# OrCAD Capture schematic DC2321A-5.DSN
size Custom; title: DC2321A: DUST APPLICATION WITH E-INK DISPLAY; rev: 5; note: DEMO CIRCUIT 2321A
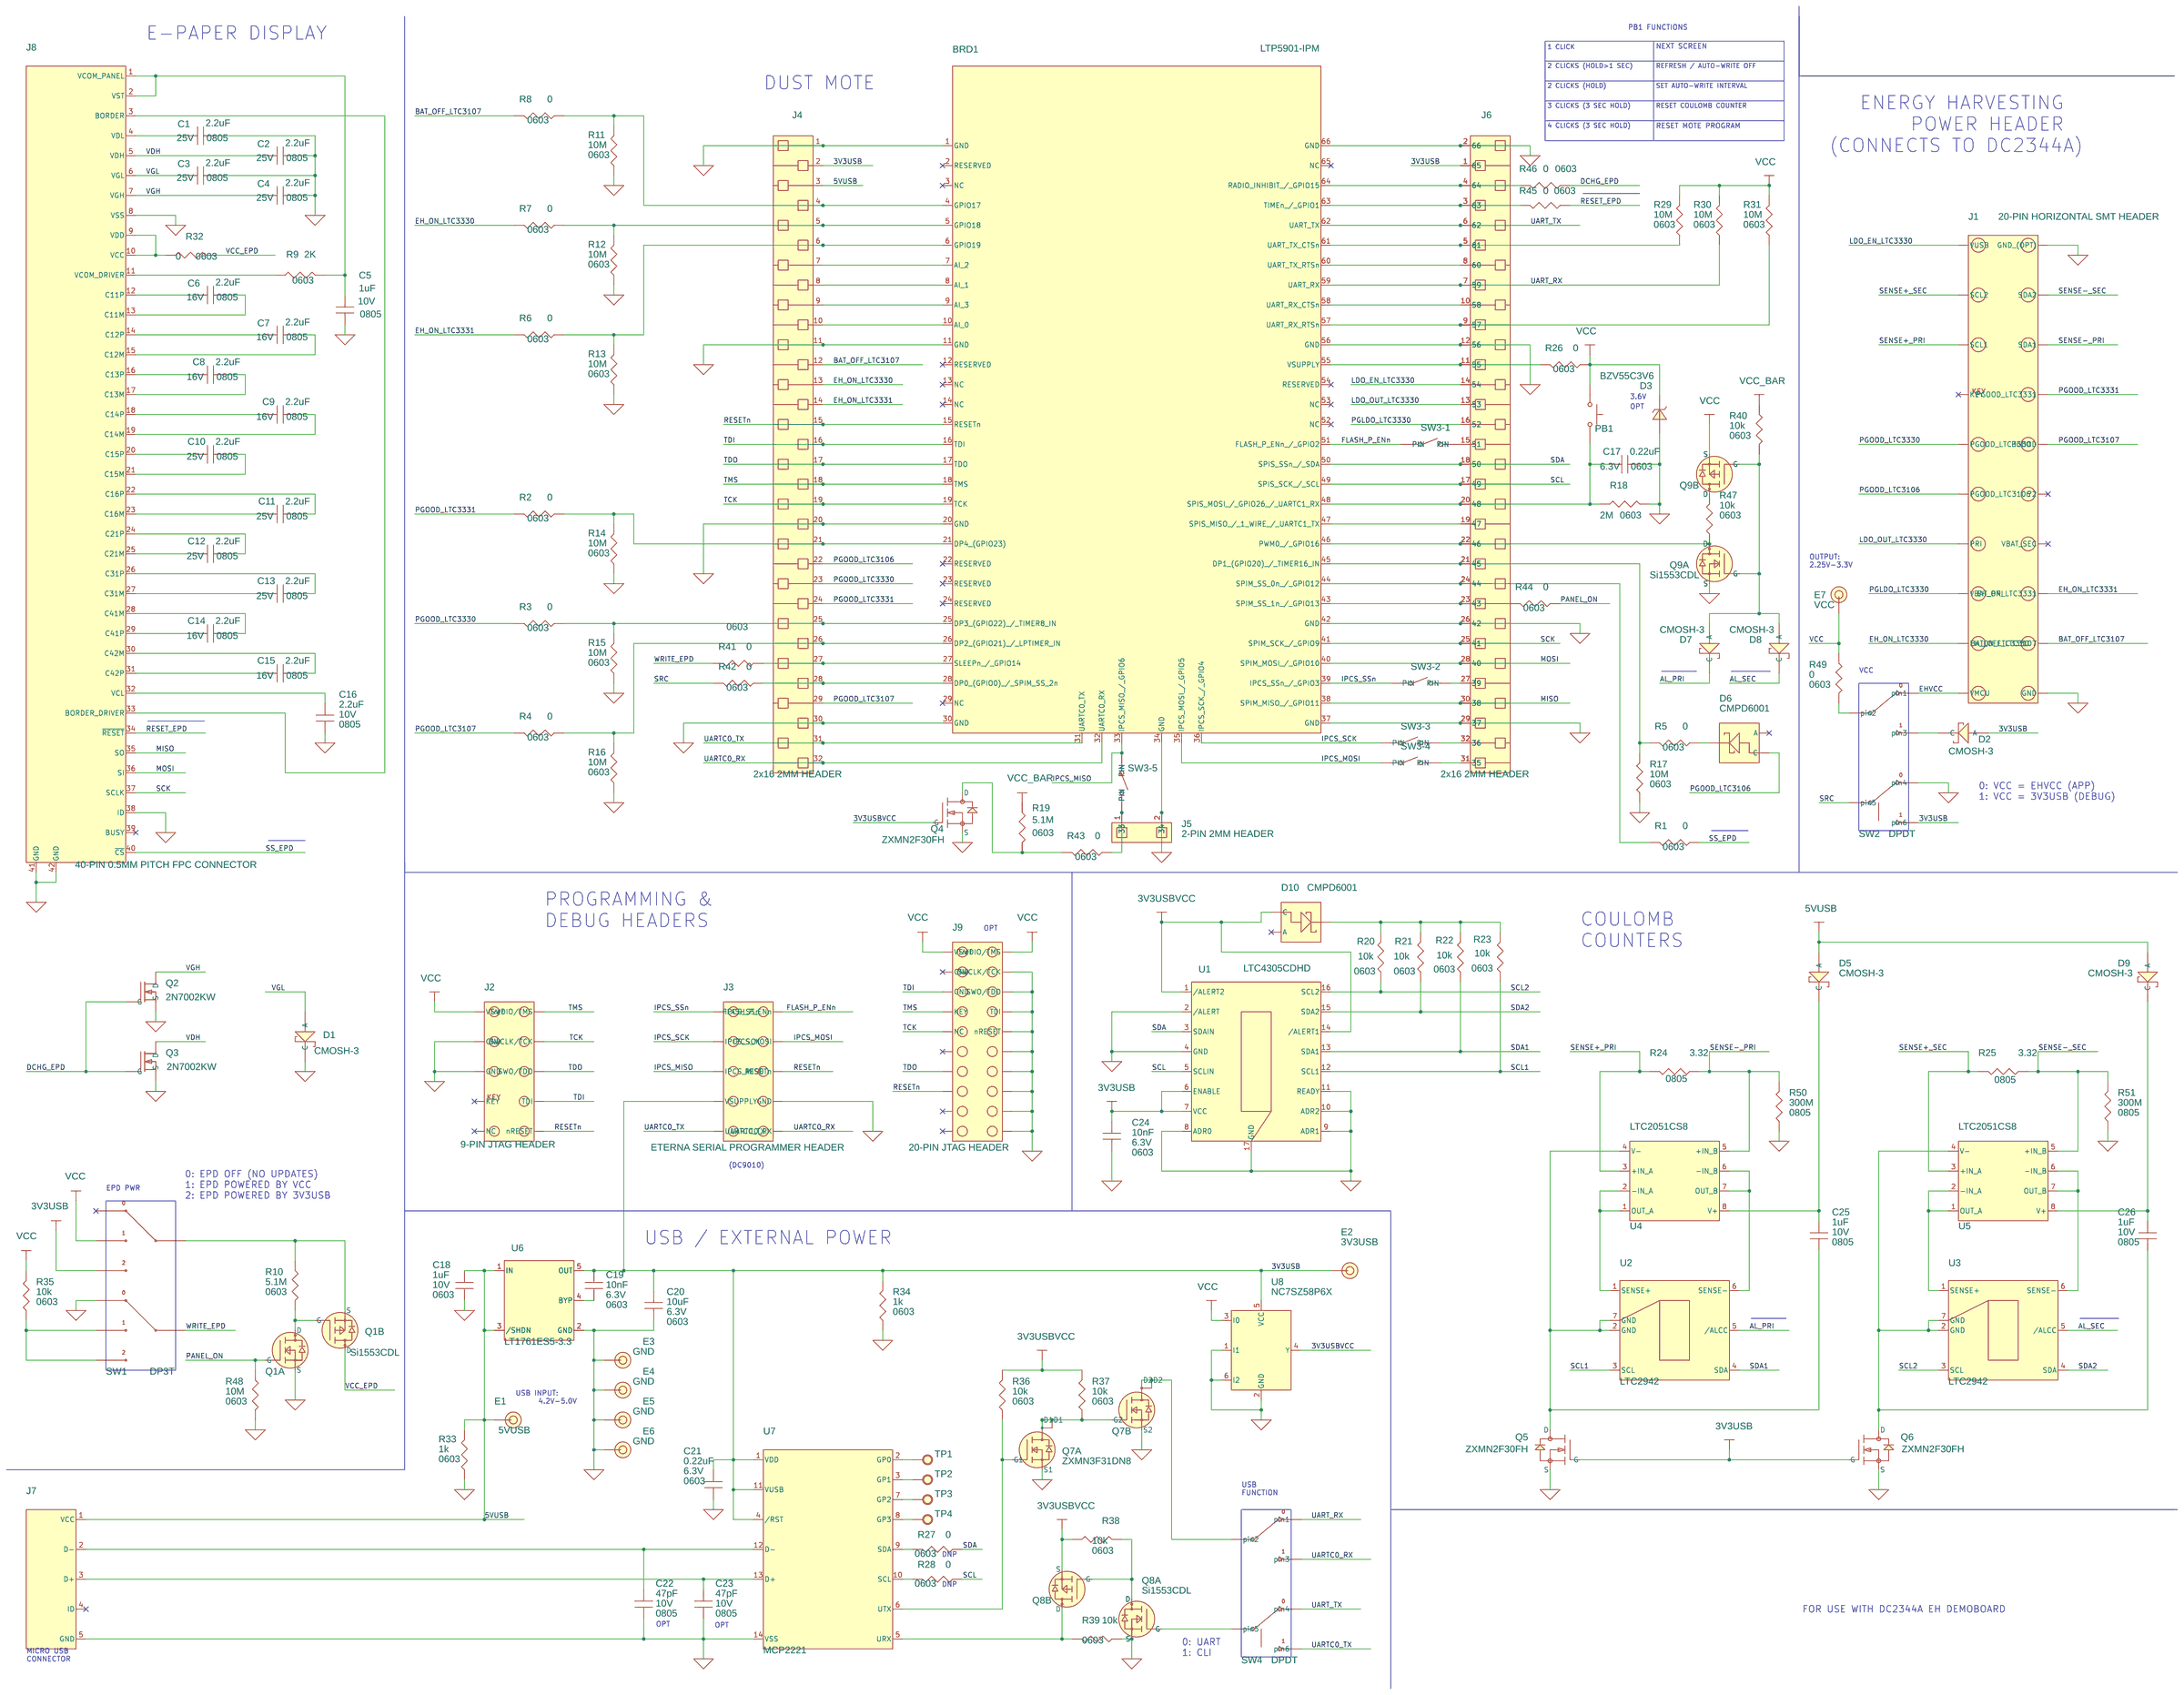
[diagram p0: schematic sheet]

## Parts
BRD1  LTP5901-IPM  [LTP5901-IPM/LTP5902-IPM]
C1  2.2uF  [0805]
C2  2.2uF  [0805]
C3  2.2uF  [0805]
C4  2.2uF  [0805]
C5  1uF  [0805]
C6  2.2uF  [0805]
C7  2.2uF  [0805]
C8  2.2uF  [0805]
C9  2.2uF  [0805]
C10  2.2uF  [0805]
C11  2.2uF  [0805]
C12  2.2uF  [0805]
C13  2.2uF  [0805]
C14  2.2uF  [0805]
C15  2.2uF  [0805]
C16  2.2uF  [0805]
C17  0.22uF  [0603]
C18  1uF  [0603]
C19  10nF  [0603]
C20  10uF  [0603]
C21  0.22uF  [0603]
C22  47pF  [0805]
C23  47pF  [0805]
C24  10nF  [0603]
C25  1uF  [0805]
C26  1uF  [0805]
D1  CMOSH-3  [SOD-523]
D2  CMOSH-3  [SOD-523]
D3  BZV55C3V6  [SOD80]
D5  CMOSH-3  [SOD-523]
D6  CMPD6001  [SOT-23]
D7  CMOSH-3  [SOD-523]
D8  CMOSH-3  [SOD-523]
D9  CMOSH-3  [SOD-523]
D10  CMPD6001  [SOT-23]
E1  5VUSB  [MILL-MAX-2308]
E2  3V3USB  [MILL-MAX-2308]
E3  GND  [MILL-MAX-2308]
E4  GND  [MILL-MAX-2308]
E5  GND  [MILL-MAX-2308]
E6  GND  [MILL-MAX-2308]
E7  VCC  [MILL-MAX-2308]
J1  20-PIN HORIZONTAL SMT HEADER  [HEADER2X10MS2.54]
J2  9-PIN JTAG HEADER  [HDR-WURTH-62201021121-2X5-1.27MM_W_KEY]
J3  ETERNA SERIAL PROGRAMMER HEADER  [HDR-WURTH-62001021121-2X5-2MM-ETERNA_HDR]
J4  2x16 2MM HEADER  [HDR-WURTH-62003221821-2X16-2MM]
J5  2-PIN 2MM HEADER  [WURTH-62000211821-2P-2MM]
J6  2x16 2MM HEADER  [HDR-WURTH-62003221821-2X16-2MM]
J7  MICRO USB CONNECTOR  [WURTH-629105136821-MICRO-USB-2.0]
J8  40-PIN 0.5MM PITCH FPC CONNECTOR  [WURTH-68714014522-40P_FPC_CONNECTOR]
J9  20-PIN JTAG HEADER  [HDR-SBH11-NBPC-D10-SM-BK]
PB1  1ApanelmountSPST  [SW-WURTH-434-111-025-826]
Q1  Si1553DL  [SC70-6]  (sections A,B)
Q2  2N7002KW  [SC70-3]
Q3  2N7002KW  [SC70-3]
Q4  ZXMN2F30FH  [ZETEX-SOT23]
Q5  ZXMN2F30FH  [ZETEX-SOT23]
Q6  ZXMN2F30FH  [ZETEX-SOT23]
Q7  ZXMN3F31DN8  [SO8]  (sections A,B)
Q8  Si1553DL  [SC70-6]  (sections A,B)
Q9  Si1553DL  [SC70-6]  (sections A,B)
R1  0  [0603]
R2  0  [0603]
R3  0  [0603]
R4  0  [0603]
R5  0  [0603]
R6  0  [0603]
R7  0  [0603]
R8  0  [0603]
R9  2K  [0603]
R10  5.1M  [0603]
R11  10M  [0603]
R12  10M  [0603]
R13  10M  [0603]
R14  10M  [0603]
R15  10M  [0603]
R16  10M  [0603]
R17  10M  [0603]
R18  2M  [0603]
R19  5.1M  [0603]
R20  10k  [0603]
R21  10k  [0603]
R22  10k  [0603]
R23  10k  [0603]
R24  3.32  [0805]
R25  3.32  [0805]
R26  0  [0603]
R27  0  [0603]
R28  0  [0603]
R29  10M  [0603]
R30  10M  [0603]
R31  10M  [0603]
R32  0  [0603]
R33  1k  [0603]
R34  1k  [0603]
R35  10k  [0603]
R36  10k  [0603]
R37  10k  [0603]
R38  10k  [0603]
R39  10k  [0603]
R40  10k  [0603]
R41  0  [0603]
R42  0  [0603]
R43  0  [0603]
R44  0  [0603]
R45  0  [0603]
R46  0  [0603]
R47  10k  [0603]
R48  10M  [0603]
R49  0  [0603]
R50  300M  [0805]
R51  300M  [0805]
SW1  DP3T  [SLIDE_SW-DP3T-CL-SB-23A-02T]
SW2  DPDT  [SLIDE-SW-CL-SB-22A]
SW3  1ApanelmountSPST  [WURTH-SW-416131160805]  (sections -1,-2,-3,-4,-5)
SW4  DPDT  [SLIDE-SW-CL-SB-22A]
TP1  Large Turret_1  [TP]
TP2  Large Turret_1  [TP]
TP3  Large Turret_1  [TP]
TP4  Large Turret_1  [TP]
U1  LTC4305CDHD  [DFN(16)(DHD)5MMX4MM]
U2  LTC2942  [DCB6DFN2X3]
U3  LTC2942  [DCB6DFN2X3]
U4  LTC2051CS8  [S8]
U5  LTC2051CS8  [S8]
U6  LT1761ES5-3.3  [SOT23-S5]
U7  MCP2221  [TSSOP14_MCP2221]
U8  NC7SZ58P6X  [SC-70]

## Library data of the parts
BRD1 = LTP5901-IPM_8
C1 = Capacitor_2_12: Voltage Rating: 25V
C2 = Capacitor_2_22: Voltage Rating: 25V
C3 = Capacitor_2_9: Voltage Rating: 25V
C4 = Capacitor_2_10: Voltage Rating: 25V
C5 = Capacitor_2_21: Voltage Rating: 10V
C6 = Capacitor_2_11: Voltage Rating: 16V
C7 = Capacitor_2_19: Voltage Rating: 16V
C8 = Capacitor_2_14: Voltage Rating: 16V
C9 = Capacitor_2_6: Voltage Rating: 16V
C10 = Capacitor_2_16: Voltage Rating: 25V
C11 = Capacitor_2_13: Voltage Rating: 25V
C12 = Capacitor_2_4: Voltage Rating: 25V
C13 = Capacitor_2_25: Voltage Rating: 25V
C14 = Capacitor_2_18: Voltage Rating: 16V
C15 = Capacitor_2_1: Voltage Rating: 16V
C16 = Capacitor_2_7: Voltage Rating: 10V
C17 = Capacitor_2_24: Voltage Rating: 6.3V
C18 = Capacitor_2: Voltage Rating: 10V
C19 = Capacitor_2_20: Voltage Rating: 6.3V
C20 = Capacitor_2_23: Voltage Rating: 6.3V
C21 = Capacitor_2_8: Voltage Rating: 6.3V
C22 = Capacitor_2_15: Voltage Rating: 10V
C23 = Capacitor_2_17: Voltage Rating: 10V
C24 = Capacitor_2_5: Voltage Rating: 6.3V
C25 = Capacitor_2_2: Voltage Rating: 10V
C26 = Capacitor_2_3: Voltage Rating: 10V
D1 D2 D5 D7-D9 = CMSH3-MA
D3 = AD589_TO_1
D6 D10 = CMSH3-MA_7
E1-E7 = E_1: STATUS: 1.6V, 1.8V, 2.0V OR 2.5V @ 15A
J1 = 20-Pin_Horizontal_SMTHeader_7
J2 = 9-PIN_JTAG_CONNECTOR_3
J3 = IN_CIRCUIT_PROGRAMMING_HEADER_1
J4 = 2x16_2MM_CONNECTOR_14
J5 = 2_PIN,_2MM_PITCH,_SOCKET_8
J6 = 2x16_2MM_CONNECTOR_18
J7 = USB_Connector_0
J8 = E-Ink_Display_6
J9 = 9-PIN_JTAG_CONNECTOR_2
PB1 = 1ApanelmountSPST_5
Q1 Q8 Q9 = NDC7001C_9: COMPONENT: Si1553CDL
Q2 Q3 = 2N7000P_TO_0
Q4-Q6 = ZVN3306_0
Q7 = NDC7001C_14
R1-R51 = RESISTOR
SW1 = SW-DP3T_0
SW2 SW4 = SW-4PDT_1
SW3 = SW-SMD-SPST-8POS_6
TP1-TP4 = Large_Turret_1
U1 = LTC4305_3
U2 U3 = LTC2943_2
U4 U5 = LT1112_0
U6 = LT1761_0
U7 = FT200XD_11
U8 = NC7SZ58P6X_1

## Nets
3V3USB: C19.1 C20.1 C21.1 C24.2 D2.2(A) E2.1(A) J3.7(VSUPPLY) J4.2 J6.1(65) Q5.1(G) Q6.1(G) R34.2 R40.1 SW1.4 SW2.6(pin6) U1.6(ENABLE) U1.7(VCC) U6.5(OUT) U7.1(VDD) U7.4(/RST) U7.11(VUSB) U8.5(VCC)
3V3USBVCC: D10.1(C) Q4.1(G) Q8.4(S) R36.1 R37.1 R38.2 U1.1(/ALERT2) U1.14(/ALERT1) U8.4(Y)
5VUSB: C18.1 D5.2(A) D9.2(A) E1.1(A) J4.3 J7.1(VCC) R33.2 U6.1(IN) U6.3(/SHDN)
GND_SIGNAL: BRD1.1(GND) BRD1.11(GND) BRD1.20(GND) BRD1.30(GND) BRD1.34(GND) BRD1.37(GND) BRD1.42(GND) BRD1.56(GND) BRD1.66(GND) C1.1 C2.1 C3.1 C4.1 C5.1 C16.2 C17.1 C18.2 C20.2 C21.2 C22.2 C23.2 C24.1 D1.1(C) D3.2(A) E3.1(A) E4.1(A) E5.1(A) E6.1(A) J1.1(GND) J1.19(GND_(OPT)) J2.3(GND) J2.5(GND) J3.8(GND) J4.1 J4.11 J4.20 J4.30 J5.2(34) J6.2(66) J6.12(56) J6.26(42) J6.29(37) J7.5(GND) J8.8(VSS) J8.38(ID) J8.41(GND) J8.42(GND) J9.4(SWCLK/TCK) J9.6(SWO/TDO) J9.8(TDI) J9.10(nRESET) J9.12 J9.14 J9.16 J9.18 J9.20 Q1.1(S) Q2.2(S) Q3.2(S) Q4.2(S) Q5.2(S) Q6.2(S) Q7.1(S1) Q7.3(S2) Q8.1(S) Q9.1(S) R11.1 R12.1 R13.1 R14.1 R15.1 R16.1 R17.1 R18.2 R33.1 R34.1 R39.2 R48.2 R50.1 R51.1 SW1.5 SW2.4(pin4) U1.2(/ALERT) U1.4(GND) U1.8(ADR0) U1.9(ADR1) U1.10(ADR2) U1.11(READY) U1.17(GND) U6.2(GND) U7.14(VSS) U8.1(I1) U8.2(GND) U8.6(I2)
VCC: D3.1(C) E7.1(A) J2.1(VTref) J9.1(VTref) J9.2(SWDIO/TMS) PB1.1(pin1) Q9.4(S) R19.1 R26.1 R29.2 R30.2 R31.2 R35.2 R49.1 SW1.2 U8.3(I0)
VCC_EPD: Q1.3(D) R32.2
AL_PRI: D7.1(C) U2.5(/ALCC)
AL_SEC: D8.1(C) U3.5(/ALCC)
BAT_OFF_LTC3107: J1.3(BAT_OFF_LTC3107) J4.12 R8.2
DCHG_EPD: Q2.1(G) Q3.1(G) R46.1
EH_ON_LTC3330: J1.4(EH_ON_LTC3330) J4.13 R7.2
EH_ON_LTC3331: J1.5(EH_ON_LTC3331) J4.14 R6.2
EHVCC: J1.2(VMCU) SW2.1(pin1)
FLASH_P_ENn: BRD1.51(FLASH_P_ENn_/_GPIO2) J3.2(FLASH_P_ENn) SW3.1(PIN)
IPCS_MISO: BRD1.33(IPCS_MISO_/_GPIO6) J3.5(IPCS_MISO) SW3.5(PIN)
IPCS_MOSI: BRD1.35(IPCS_MOSI_/_GPIO5) J3.4(IPCS_MOSI) SW3.4(PIN)
IPCS_SCK: BRD1.36(IPCS_SCK_/_GPIO4) J3.3(IPCS_SCK) SW3.3(PIN)
IPCS_SSn: BRD1.39(IPCS_SSn_/_GPIO3) J3.1(IPCS_SSn) SW3.2(PIN)
LDO_EN_LTC3330: J1.20(VUSB) J6.14(54)
LDO_OUT_LTC3330: J1.8(PRI) J6.13(53)
MISO: BRD1.38(SPIM_MISO_/_GPIO11) J6.30(38) J8.35(SO)
MOSI: BRD1.40(SPIM_MOSI_/_GPIO10) J6.28(40) J8.36(SI)
PANEL_ON: Q1.2(G) R44.1 R48.1
PGLDO_LTC3330: J1.6(VBAT_PRI) J6.16(52)
PGOOD_LTC3106: D6.1(C) J1.10(PGOOD_LTC3106) J4.22
PGOOD_LTC3107: J1.11(PGOOD) J4.29 R4.2
PGOOD_LTC3330: J1.12(PGOOD_LTC3330) J4.23 R3.2
PGOOD_LTC3331: J1.13(PGOOD_LTC3331) J4.24 R2.2
RESET_EPD: J8.34(~{RESET}) R45.1
RESETn: BRD1.15(RESETn) J2.10(nRESET) J3.6(RESETn) J4.15 J9.15
SCK: BRD1.41(SPIM_SCK_/_GPIO9) J6.25(41) J8.37(SCLK)
SCL: BRD1.49(SPIS_SCK_/_SCL) J6.17(49) R28.1 U1.5(SCLIN)
SCL1: R23.1 U1.12(SCL1) U2.3(SCL)
SCL2: R20.1 U1.16(SCL2) U3.3(SCL)
SDA: BRD1.50(SPIS_SSn_/_SDA) J6.18(50) R27.1 U1.3(SDAIN)
SDA1: R22.1 U1.13(SDA1) U2.4(SDA)
SDA2: R21.1 U1.15(SDA2) U3.4(SDA)
SENSE+_PRI: J1.16(SCL1) R24.2 U4.3(+IN_A)
SENSE+_SEC: J1.18(SCL2) R25.2 U5.3(+IN_A)
SENSE-_PRI: J1.15(SDA1) R24.1 R50.2 U4.5(+IN_B)
SENSE-_SEC: J1.17(SDA2) R25.1 R51.2 U5.5(+IN_B)
SRC: R42.2 SW2.5(pin5)
SS_EPD: J8.40(~{CS}) R1.1
TCK: BRD1.19(TCK) J2.4(SWCLK/TCK) J4.19 J9.9(NC)
TDI: BRD1.16(TDI) J2.8(TDI) J4.16 J9.5(GND)
TDO: BRD1.17(TDO) J2.6(SWO/TDO) J4.17 J9.13
TMS: BRD1.18(TMS) J2.2(SWDIO/TMS) J4.18 J9.7(KEY)
UART_RX: BRD1.59(UART_RX) J6.7(59) R30.1 SW4.1(pin1)
UART_TX: BRD1.62(UART_TX) J6.6(62) SW4.4(pin4)
UARTC0_RX: BRD1.32(UARTC0_RX) J3.10(UARTC0_RX) J4.32 SW4.3(pin3)
UARTC0_TX: BRD1.31(UARTC0_TX) J3.9(UARTC0_TX) J4.31 SW4.6(pin6)
VDH: C2.2 J8.5(VDH) Q3.3(D)
VGH: C4.2 J8.7(VGH) Q2.3(D)
VGL: C3.2 D1.2(A) J8.6(VGL)
WRITE_EPD: R41.2 SW1.7
N2135616: C22.1 J7.2(D-) U7.12(D-)
N2135985: C23.1 J7.3(D+) U7.13(D+)
N2567129: D10.3 R20.2 R21.2 R22.2 R23.2
N2983874: C5.2 J8.1(VCOM_PANEL) J8.2(VST) R9.2
N2983878: J8.9(VDD) J8.10(VCC) R32.1
N2983960: C1.2 J8.4(VDL)
N2984004: J8.3(BORDER) J8.33(BORDER_DRIVER)
N2984054: C16.1 J8.32(VCL)
N2984140: C14.2 J8.29(C41P)
N2984144: C14.1 J8.28(C41M)
N2984156: C13.2 J8.27(C31M)
N2984160: C13.1 J8.26(C31P)
N2984216: C12.2 J8.25(C21M)
N2984220: C12.1 J8.24(C21P)
N2984232: C11.2 J8.23(C16M)
N2984236: C11.1 J8.22(C16P)
N2984270: C10.1 J8.21(C15M)
N2984282: C10.2 J8.20(C15P)
N2984314: C9.1 J8.19(C14M)
N2984332: C9.2 J8.18(C14P)
N2984408: C8.1 J8.17(C13M)
N2984420: C8.2 J8.16(C13P)
N2984424: C7.1 J8.15(C12M)
N2984436: C7.2 J8.14(C12P)
N2984440: J8.11(VCOM_DRIVER) R9.1
N2984470: C6.1 J8.13(C11M)
N2984486: C6.2 J8.12(C11P)
N3276140: U3.6(SENSE-) U5.6(-IN_B) U5.7(OUT_B)
N3276190: C26.1 D9.1(C) U5.8(V+)
N3276230: C26.2 Q6.3(D) U3.2(GND) U3.7(GND) U5.4(V-)
N3276392: U2.6(SENSE-) U4.6(-IN_B) U4.7(OUT_B)
N3276498: C25.1 D5.1(C) U4.8(V+)
N3276538: C25.2 Q5.3(D) U2.2(GND) U2.7(GND) U4.4(V-)
N3287242: U2.1(SENSE+) U4.1(OUT_A) U4.2(-IN_A)
N3857968: BRD1.57(UART_RX_RTSn) J6.9(57) R31.1
N3857974: BRD1.47(SPIS_MISO_/_1_WIRE_/_UARTC1_TX) J6.19(47)
N3858144: BRD1.46(PWM0_/_GPIO16) J6.22(46) Q9.6(D) R47.1
N3858174: BRD1.63(TIMEn_/_GPIO1) J6.3(63) R45.2
N3858190: BRD1.64(RADIO_INHIBIT_/_GPIO15) J6.4(64) R46.2
N3858202: BRD1.61(UART_TX_CTSn) J6.5(61) R29.1
N3858208: BRD1.60(UART_TX_RTSn) J6.8(60)
N3858224: BRD1.58(UART_RX_CTSn) J6.10(58)
N4109512: U3.1(SENSE+) U5.1(OUT_A) U5.2(-IN_A)
N4322068: C19.2 U6.4(BYP)
N4826260: BRD1.44(SPIM_SS_0n_/_GPIO12) J6.24(44) R1.2
N4829499: BRD1.43(SPIM_SS_1n_/_GPIO13) J6.23(43) R44.2
N4893985: BRD1.45(DP1_(GPIO20)_/_TIMER16_IN) J6.21(45) R5.2 R17.2
N4910566: BRD1.4(GPIO17) J4.4 R8.1 R11.2
N4940922: BRD1.6(GPIO19) J4.6 R6.1 R13.2
N5057493: BRD1.21(DP4_(GPIO23)) J4.21 R2.1 R14.2
N5102898: BRD1.55(VSUPPLY) J6.11(55) R26.2
N5102906: BRD1.48(SPIS_MOSI_/_GPIO26_/_UARTC1_RX) C17.2 J6.20(48) PB1.2(pin2) R18.1
N5251768: BRD1.5(GPIO18) J4.5 R7.1 R12.2
N5256158: BRD1.7(AI_2) J4.7
N5256787: BRD1.8(AI_1) J4.8
N5257417: BRD1.9(AI_3) J4.9
N5258048: BRD1.10(AI_0) J4.10
N5273289: BRD1.25(DP3_(GPIO22)_/_TIMER8_IN) J4.25 R3.1 R15.2
N5273928: BRD1.26(DP2_(GPIO21)_/_LPTIMER_IN) J4.26 R4.1 R16.2
N5276494: BRD1.27(SLEEPn_/_GPIO14) J4.27 R41.1
N5277137: BRD1.28(DP0_(GPIO0)_/_SPIM_SS_2n) J4.28 R42.1
N6225294: TP4.1 U7.8(GP3)
N6225300: TP1.1 U7.2(GP0)
N6225306: TP2.1 U7.3(GP1)
N6225318: TP3.1 U7.7(GP2)
N6230331: Q1.5(G) Q1.6(D) R10.2
N6230377: Q1.4(S) R10.1 SW1.3
N6422867: C15.1 J8.30(C42M)
N6422881: C15.2 J8.31(C42P)
N6469881: D2.1(C) SW2.3(pin3)
N6498048: R27.2 U7.9(SDA)
N6498063: R28.2 U7.10(SCL)
N6558377: Q8.5(G) Q8.6(D) R38.1
N6558415: Q8.3(D) R39.1 U7.5(URX)
N6560836: Q7.2(G1) R36.2 U7.6(UTX)
N6560855: Q7.5(D2) Q7.6(D2) SW4.2(pin2)
N6563136: Q7.4(G2) Q7.7(D1) Q7.8(D1) R37.2
N6611339: Q8.2(G) SW4.5(pin5)
N6615827: R35.1 SW1.6 SW1.8
N6643529: J6.27(39) SW3.9(PIN)
N6643563: J6.32(36) SW3.8(PIN)
N6643589: J6.31(35) SW3.7(PIN)
N6648994: Q4.3(D) R19.2 R43.2
N6648999: J5.1(33) R43.1 SW3.6(PIN)
N6680690: D7.2(A) D8.2(A) Q9.2(G) Q9.5(G) R40.2
N6692963: D6.3 R5.1
N6695258: J6.15(51) SW3.10(PIN)
N6695261: Q9.3(D) R47.2
N6702681: R49.2 SW2.2(pin2)

Not connected (* = marked no-connect by the designer): BRD1 2(RESERVED)* 3(NC)* 12(RESERVED)* 13(NC)* 14(NC)* 22(RESERVED)* 23(RESERVED)* 24(RESERVED)* 29(NC)* 52(NC)* 53(NC)* 54(RESERVED)* 65(NC)*; D6 2(A)*; D10 2(A)*; J1 7(VBAT_SEC)* 9(?2)* 14(KEY)*; J2 7(KEY)* 9(NC)*; J7 4(ID)*; J8 39(BUSY)*; J9 3(GND)* 11* 17* 19*; SW1 1*

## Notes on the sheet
- E-PAPER DISPLAY
- PB1 FUNCTIONS
- 1 CLICK
- NEXT SCREEN
- 2 CLICKS (HOLD>1 SEC)
- REFRESH / AUTO-WRITE OFF
- DUST MOTE
- 2 CLICKS (HOLD)
- SET AUTO-WRITE INTERVAL
- 3 CLICKS (3 SEC HOLD)
- RESET COULOMB COUNTER
- ENERGY HARVESTING
          POWER HEADER
  (CONNECTS TO DC2344A)
- 4 CLICKS (3 SEC HOLD)
- RESET MOTE PROGRAM
- 3.6V
- OPT
- OUTPUT:
  2.25V-3.3V
- VCC
- 0: VCC = EHVCC (APP)
  1: VCC = 3V3USB (DEBUG)
- PROGRAMMING &
  DEBUG HEADERS
- COULOMB
  COUNTERS
- OPT
- (DC9010)
- 0: EPD OFF (NO UPDATES)
  1: EPD POWERED BY VCC
  2: EPD POWERED BY 3V3USB
- EPD PWR
- USB / EXTERNAL POWER
- USB INPUT:
        4.2V-5.0V
- USB
  FUNCTION
- DNP
- DNP
- FOR USE WITH DC2344A EH DEMOBOARD
- OPT
- OPT
- 0: UART
  1: CLI
- MICRO USB
  CONNECTOR
